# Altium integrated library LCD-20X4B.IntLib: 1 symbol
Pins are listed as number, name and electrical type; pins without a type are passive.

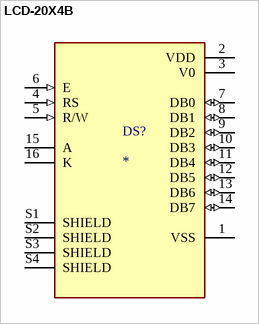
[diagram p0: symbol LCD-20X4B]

## LCD-20X4B
designator DS?
Display Development Tools 20X4 CHARACTER BLUE LCD W/BACKLIGHT; MP: LCD-20X4B
footprint LCD_LCD-20X4B
pins: 1 VSS (power), 2 VDD (power), 3 V0 (power), 4 RS (in), 5 R/W (in), 6 E (in), 7 DB0 (io), 8 DB1 (io), 9 DB2 (io), 10 DB3 (io), 11 DB4 (io), 12 DB5 (io), 13 DB6 (io), 14 DB7 (io), 15 A, 16 K, S1 SHIELD, S2 SHIELD, S3 SHIELD, S4 SHIELD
